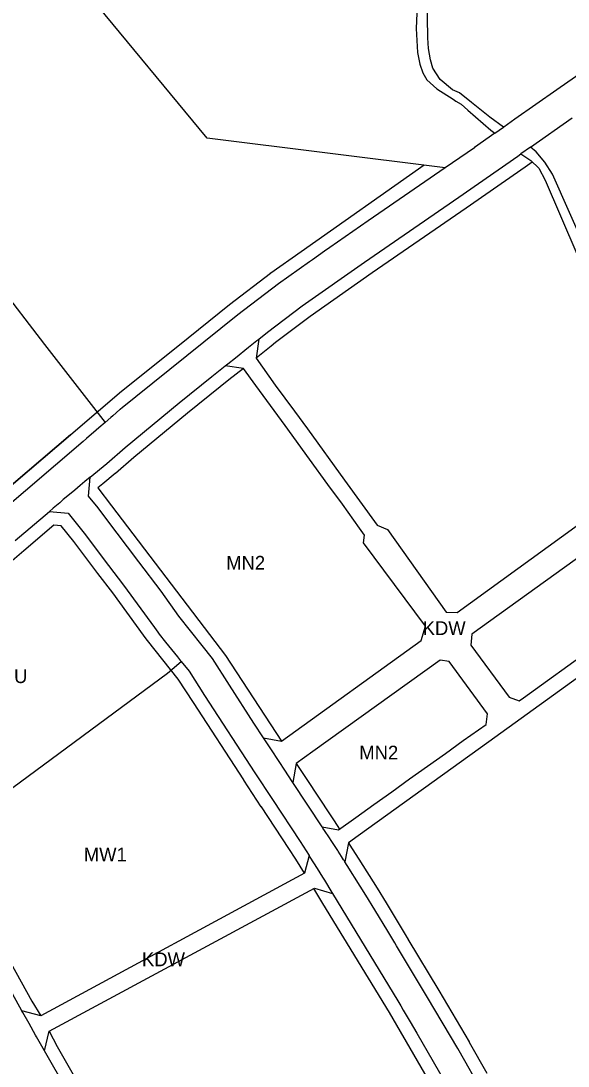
# Model space of a CAD drawing. Extents: x 7435758 to 7439981, y 5550649 to 5554049.
# Drawn here: x 7437642.5 to 7437849, y 5551609 to 5552003.8 of the extents above; entities that cross this region are included whole.
import ezdxf

# ---------------------------------------------------------------- set-up
doc = ezdxf.new("R2010")
doc.units = 0
for name, color, linetype in [('linie_rozgraniczające', 7, 'Continuous'), ('linie_zabudowy_nieprzekraczalne', 7, 'Continuous'), ('oznaczenia_przeznaczen', 7, 'Continuous')]:
    doc.layers.add(name, color=color, linetype=linetype)

msp = doc.modelspace()

# ---------------------------------------------------------------- linework, layer by layer
at = {"layer": 'linie_rozgraniczające'}
for p, q in [((7437712.83, 5551959.48), (7437577.43, 5552123.38)), ((7437796.11, 5551997.41), (7437795.23, 5552040.98)), ((7437792.45, 5552018.67), (7437791.72, 5552000.89)), ((7437791.72, 5552000.89), (7437792.18, 5551991.78)), ((7437796.28, 5551993.3), (7437796.11, 5551997.41)), ((7437792.18, 5551991.78), (7437793.09, 5551987.39)), ((7437797.12, 5551989.1), (7437796.28, 5551993.3)), ((7437793.09, 5551987.39), (7437794.21, 5551984.18)), ((7437797.95, 5551985.86), (7437797.12, 5551989.1)), ((7437800.76, 5551981.58), (7437797.95, 5551985.86)), ((7437794.21, 5551984.18), (7437795.76, 5551981.53)), ((7437854.78, 5551984.69), (7437844.78, 5551977.68)), ((7437795.76, 5551981.53), (7437799.51, 5551978.16)), ((7437799.51, 5551978.16), (7437805.64, 5551974.16)), ((7437805.36, 5551977.76), (7437800.76, 5551981.58)), ((7437808.05, 5551976.66), (7437805.36, 5551977.76)), ((7437805.64, 5551974.16), (7437806.67, 5551973.51)), ((7437812.58, 5551972.99), (7437808.05, 5551976.66)), ((7437844.78, 5551977.68), (7437828.97, 5551966.61)), ((7437806.67, 5551973.51), (7437808.61, 5551972.29)), ((7437808.61, 5551972.29), (7437811.23, 5551970.05)), ((7437811.23, 5551970.05), (7437819.85, 5551962.54)), ((7437819.46, 5551967.45), (7437812.58, 5551972.99)), ((7437824.7, 5551963.61), (7437819.46, 5551967.45)), ((7437828.97, 5551966.61), (7437824.78, 5551963.66)), ((7437834.89, 5551956.1), (7437850.63, 5551967.13)), ((7437819.85, 5551962.54), (7437821.43, 5551961.32)), ((7437821.43, 5551961.32), (7437824.7, 5551963.61)), ((7437824.78, 5551963.66), (7437824.7, 5551963.61)), ((7437802.61, 5551948.27), (7437712.83, 5551959.48)), ((7437821.43, 5551961.32), (7437813.73, 5551955.92)), ((7437813.65, 5551955.89), (7437802.61, 5551948.27)), ((7437813.66, 5551955.87), (7437813.65, 5551955.89)), ((7437813.73, 5551955.92), (7437813.66, 5551955.87)), ((7437834.89, 5551956.1), (7437831.21, 5551953.52)), ((7437837.03, 5551954.33), (7437834.89, 5551956.1)), ((7437840.29, 5551950.48), (7437837.03, 5551954.33)), ((7437807.74, 5551937.2), (7437830.01, 5551952.68)), ((7437830.01, 5551952.68), (7437830.04, 5551952.7)), ((7437830.04, 5551952.7), (7437831.21, 5551953.52)), ((7437831.21, 5551953.52), (7437834.97, 5551951.01)), ((7437834.97, 5551951.01), (7437837.94, 5551948.15)), ((7437843.13, 5551945.94), (7437840.29, 5551950.48)), ((7437802.61, 5551948.27), (7437777.58, 5551930.98)), ((7437837.94, 5551948.15), (7437840.36, 5551943.66)), ((7437840.36, 5551943.66), (7437852.28, 5551915.86)), ((7437855.94, 5551916.89), (7437843.13, 5551945.94)), ((7437772.17, 5551912.67), (7437807.74, 5551937.2)), ((7437777.58, 5551930.98), (7437773.57, 5551928.21)), ((7437773.57, 5551928.21), (7437759.14, 5551918.25)), ((7437757.12, 5551916.83), (7437752.5, 5551913.57)), ((7437759.14, 5551918.25), (7437757.12, 5551916.83)), ((7437627.25, 5551912.88), (7437651.38, 5551881.6)), ((7437751.4, 5551912.79), (7437739.68, 5551904.52)), ((7437748.7, 5551896.2), (7437772.17, 5551912.67)), ((7437752.15, 5551913.32), (7437751.4, 5551912.79)), ((7437752.5, 5551913.57), (7437752.15, 5551913.32)), ((7437739.68, 5551904.52), (7437724.32, 5551892.73)), ((7437735.5, 5551886.21), (7437748.7, 5551896.2)), ((7437724.32, 5551892.73), (7437685.84, 5551861.8)), ((7437732.24, 5551883.6), (7437731.24, 5551876.4)), ((7437731.52, 5551883.02), (7437732.24, 5551883.6)), ((7437732.24, 5551883.6), (7437735.5, 5551886.21)), ((7437651.38, 5551881.6), (7437674.25, 5551852.12)), ((7437723.47, 5551876.58), (7437728.36, 5551880.49)), ((7437728.36, 5551880.49), (7437731.52, 5551883.02)), ((7437720.62, 5551874.3), (7437723.47, 5551876.58)), ((7437731.24, 5551876.4), (7437738.41, 5551866.24)), ((7437714.52, 5551869.41), (7437719.6, 5551873.48)), ((7437719.6, 5551873.48), (7437720.62, 5551874.3)), ((7437726.51, 5551872.44), (7437719.6, 5551873.48)), ((7437731.2, 5551866.04), (7437726.51, 5551872.44)), ((7437702.19, 5551859.51), (7437714.52, 5551869.41)), ((7437742.22, 5551851.01), (7437731.2, 5551866.04)), ((7437738.41, 5551866.24), (7437745.69, 5551856.39)), ((7437681.86, 5551842.68), (7437702.19, 5551859.51)), ((7437685.84, 5551861.8), (7437681.99, 5551858.68)), ((7437679.84, 5551856.95), (7437677.13, 5551854.61)), ((7437679.98, 5551857.06), (7437679.84, 5551856.95)), ((7437680.88, 5551857.78), (7437679.98, 5551857.06)), ((7437681.99, 5551858.68), (7437680.88, 5551857.78)), ((7437745.69, 5551856.39), (7437750.65, 5551849.65)), ((7437674.25, 5551852.12), (7437671.9, 5551850.1)), ((7437676.47, 5551854.04), (7437674.25, 5551852.12)), ((7437677.13, 5551854.61), (7437676.47, 5551854.04)), ((7437670.89, 5551849.23), (7437667.25, 5551846.09)), ((7437671.9, 5551850.1), (7437670.89, 5551849.23)), ((7437742.22, 5551851), (7437742.22, 5551851.01)), ((7437751.47, 5551838.2), (7437742.22, 5551851)), ((7437750.65, 5551849.65), (7437764.61, 5551830.36)), ((7437665.96, 5551844.96), (7437632.46, 5551816.42)), ((7437667.24, 5551846.05), (7437665.96, 5551844.96)), ((7437667.25, 5551846.05), (7437667.24, 5551846.05)), ((7437667.25, 5551846.09), (7437667.25, 5551846.05)), ((7437674.9, 5551836.66), (7437681.86, 5551842.68)), ((7437668.66, 5551831.46), (7437674.9, 5551836.66)), ((7437758.35, 5551828.7), (7437751.47, 5551838.2)), ((7437664.79, 5551828.24), (7437662.82, 5551826.59)), ((7437666.62, 5551829.76), (7437664.79, 5551828.24)), ((7437668.66, 5551831.46), (7437666.62, 5551829.76)), ((7437667.96, 5551824.32), (7437668.66, 5551831.46)), ((7437763.84, 5551821.23), (7437758.35, 5551828.7)), ((7437764.61, 5551830.36), (7437776.99, 5551813.28)), ((7437662.82, 5551826.59), (7437659.51, 5551823.84)), ((7437671.6, 5551819.82), (7437667.96, 5551824.32)), ((7437807.11, 5551780.31), (7437871.35, 5551826.92)), ((7437657.13, 5551821.81), (7437654.66, 5551819.7)), ((7437658.48, 5551822.96), (7437657.13, 5551821.81)), ((7437659.51, 5551823.84), (7437658.48, 5551822.96)), ((7437770.29, 5551812.25), (7437763.84, 5551821.23)), ((7437640.35, 5551807.5), (7437653.28, 5551818.53)), ((7437654.66, 5551819.7), (7437653.28, 5551818.53)), ((7437653.28, 5551818.53), (7437660.32, 5551817.86)), ((7437660.32, 5551817.86), (7437666.39, 5551810.24)), ((7437674.59, 5551815.98), (7437671.6, 5551819.82)), ((7437877.2, 5551818.71), (7437812.75, 5551772.12)), ((7437687.04, 5551799.53), (7437674.59, 5551815.98)), ((7437772.17, 5551809.6), (7437770.29, 5551812.25)), ((7437776.99, 5551813.28), (7437780.9, 5551811.67)), ((7437666.39, 5551810.24), (7437675.56, 5551798.13)), ((7437771.76, 5551806.62), (7437772.17, 5551809.6)), ((7437780.9, 5551811.67), (7437803.06, 5551780.46)), ((7437795.17, 5551775.15), (7437771.76, 5551806.62)), ((7437675.56, 5551798.13), (7437681.15, 5551790.72)), ((7437695.36, 5551788.35), (7437687.04, 5551799.53)), ((7437681.15, 5551790.72), (7437692.85, 5551774.66)), ((7437702.04, 5551778.99), (7437695.36, 5551788.35)), ((7437710.94, 5551767.9), (7437702.04, 5551778.99)), ((7437803.06, 5551780.46), (7437807.11, 5551780.31)), ((7437692.85, 5551774.66), (7437694.15, 5551772.85)), ((7437694.15, 5551772.85), (7437694.43, 5551772.51)), ((7437793.51, 5551769.78), (7437795.17, 5551775.15)), ((7437694.43, 5551772.51), (7437694.7, 5551772.16)), ((7437694.7, 5551772.16), (7437697.09, 5551769.19)), ((7437697.09, 5551769.19), (7437701.61, 5551763.54)), ((7437740.84, 5551731.77), (7437793.51, 5551769.78)), ((7437812.75, 5551772.12), (7437812.29, 5551768.05)), ((7437714.81, 5551763.01), (7437710.94, 5551767.9)), ((7437812.29, 5551768.05), (7437826.8, 5551748.37)), ((7437866.87, 5551766.02), (7437819.07, 5551731.54)), ((7437832.18, 5551748.17), (7437860.01, 5551768.18)), ((7437697.86, 5551757.42), (7437703.01, 5551761.8)), ((7437701.61, 5551763.54), (7437702.78, 5551762.08)), ((7437702.78, 5551762.08), (7437702.87, 5551761.97)), ((7437702.87, 5551761.97), (7437702.97, 5551761.85)), ((7437702.97, 5551761.85), (7437703.01, 5551761.8)), ((7437703.01, 5551761.8), (7437705.95, 5551758.13)), ((7437721.23, 5551752.85), (7437714.81, 5551763.01)), ((7437800.68, 5551762.28), (7437752.72, 5551727.88)), ((7437804.12, 5551761.79), (7437800.68, 5551762.28)), ((7437818.64, 5551742.12), (7437804.12, 5551761.79)), ((7437608.38, 5551691.31), (7437697.86, 5551757.42)), ((7437705.95, 5551758.13), (7437711.81, 5551749.05)), ((7437711.81, 5551749.05), (7437730.8, 5551719.8)), ((7437730.46, 5551738.54), (7437721.23, 5551752.85)), ((7437826.8, 5551748.37), (7437830.59, 5551747.03)), ((7437830.59, 5551747.03), (7437832.18, 5551748.17)), ((7437818.07, 5551738.09), (7437818.64, 5551742.12)), ((7437734.09, 5551733.01), (7437730.46, 5551738.54)), ((7437809.48, 5551731.95), (7437818.07, 5551738.09)), ((7437736.81, 5551728.86), (7437734.09, 5551733.01)), ((7437734.09, 5551733.01), (7437740.84, 5551731.77)), ((7437819.07, 5551731.54), (7437769.74, 5551695.94)), ((7437802.72, 5551727.13), (7437809.48, 5551731.95)), ((7437737.1, 5551728.42), (7437736.81, 5551728.86)), ((7437742.35, 5551720.44), (7437737.1, 5551728.42)), ((7437752.72, 5551727.88), (7437746.4, 5551723.35)), ((7437795.96, 5551722.3), (7437802.72, 5551727.13)), ((7437746.4, 5551723.35), (7437745.15, 5551716.18)), ((7437789.21, 5551717.48), (7437795.96, 5551722.3)), ((7437730.8, 5551719.8), (7437737.41, 5551709.74)), ((7437743.24, 5551719.08), (7437742.35, 5551720.44)), ((7437745.15, 5551716.18), (7437743.24, 5551719.08)), ((7437782.46, 5551712.64), (7437789.21, 5551717.48)), ((7437756.16, 5551699.44), (7437745.15, 5551716.18)), ((7437737.41, 5551709.74), (7437747.86, 5551693.88)), ((7437775.71, 5551707.81), (7437782.46, 5551712.64)), ((7437768.96, 5551702.97), (7437775.71, 5551707.81)), ((7437762.38, 5551698.26), (7437768.96, 5551702.97)), ((7437756.5, 5551698.93), (7437756.16, 5551699.44)), ((7437756.16, 5551699.44), (7437762.38, 5551698.26)), ((7437757.1, 5551698.02), (7437756.5, 5551698.93)), ((7437757.13, 5551697.98), (7437757.1, 5551698.02)), ((7437758.92, 5551695.26), (7437757.13, 5551697.98)), ((7437747.86, 5551693.88), (7437751.24, 5551688.54)), ((7437759.61, 5551694.2), (7437758.92, 5551695.26)), ((7437762.07, 5551690.41), (7437759.61, 5551694.2)), ((7437769.74, 5551695.94), (7437766.13, 5551693.34)), ((7437762.19, 5551690.22), (7437762.07, 5551690.41)), ((7437763.48, 5551688.17), (7437762.19, 5551690.22)), ((7437766.13, 5551693.34), (7437764.77, 5551686.13)), ((7437751.24, 5551688.54), (7437749.48, 5551681.86)), ((7437751.24, 5551688.54), (7437751.6, 5551687.96)), ((7437751.6, 5551687.96), (7437752.96, 5551685.82)), ((7437752.96, 5551685.82), (7437754.29, 5551683.71)), ((7437764.25, 5551686.95), (7437763.48, 5551688.17)), ((7437764.46, 5551686.62), (7437764.25, 5551686.95)), ((7437764.77, 5551686.13), (7437764.46, 5551686.62)), ((7437765.6, 5551684.81), (7437764.77, 5551686.13)), ((7437749.48, 5551681.86), (7437650.01, 5551628.04)), ((7437754.29, 5551683.71), (7437754.3, 5551683.71)), ((7437754.3, 5551683.71), (7437756.33, 5551680.37)), ((7437770.51, 5551677.02), (7437765.6, 5551684.81)), ((7437756.33, 5551680.37), (7437757.05, 5551679.19)), ((7437757.05, 5551679.19), (7437759.81, 5551674.64)), ((7437653.08, 5551622.16), (7437753.28, 5551676.25)), ((7437753.28, 5551676.25), (7437760.06, 5551674.24)), ((7437759.81, 5551674.64), (7437760.06, 5551674.24)), ((7437760.06, 5551674.24), (7437784.75, 5551633.67)), ((7437772.72, 5551673.52), (7437770.51, 5551677.02)), ((7437776.12, 5551668.07), (7437772.72, 5551673.52)), ((7437780.98, 5551659.98), (7437776.12, 5551668.07)), ((7437783.62, 5551655.58), (7437780.98, 5551659.98)), ((7437783.61, 5551655.56), (7437783.62, 5551655.58)), ((7437784.29, 5551654.45), (7437783.61, 5551655.56)), ((7437795.92, 5551634.99), (7437784.29, 5551654.45)), ((7437642.86, 5551629.92), (7437629.36, 5551654.17)), ((7437807.38, 5551615.63), (7437795.92, 5551634.99)), ((7437784.75, 5551633.67), (7437785.86, 5551631.84)), ((7437785.86, 5551631.84), (7437786.82, 5551630.18)), ((7437643.23, 5551629.25), (7437642.86, 5551629.92)), ((7437650.01, 5551628.04), (7437642.86, 5551629.92)), ((7437645.57, 5551625.05), (7437643.23, 5551629.25)), ((7437786.82, 5551630.18), (7437789.4, 5551625.73)), ((7437647.97, 5551620.75), (7437645.57, 5551625.05)), ((7437789.4, 5551625.73), (7437791.88, 5551621.44)), ((7437648.35, 5551620.09), (7437647.97, 5551620.75)), ((7437650.87, 5551615.67), (7437648.35, 5551620.09)), ((7437651.34, 5551614.85), (7437653.08, 5551622.16)), ((7437791.88, 5551621.44), (7437814.86, 5551581.73)), ((7437651.34, 5551614.85), (7437650.87, 5551615.67)), ((7437701.57, 5551526.92), (7437651.34, 5551614.85)), ((7437810.02, 5551611.01), (7437807.38, 5551615.63)), ((7437814.48, 5551603.18), (7437810.02, 5551611.01))]:
    msp.add_line(p, q, dxfattribs=at)
at = {"layer": 'linie_zabudowy_nieprzekraczalne'}
msp.add_line((7437661.22, 5551847.49), (7437629.25, 5551820.25), dxfattribs=at)
for points in [[(7437835.42, 5551950.37), (7437832.87, 5551948.58), (7437832.86, 5551948.57), (7437810.59, 5551933.09), (7437810.58, 5551933.08), (7437775.02, 5551908.57), (7437751.64, 5551892.16), (7437738.57, 5551882.27), (7437736.92, 5551880.95), (7437731.24, 5551876.4)], [(7437629.25, 5551820.25), (7437661.22, 5551847.49), (7437661.27, 5551847.53), (7437680.48, 5551863.89), (7437701.66, 5551880.93), (7437721.18, 5551896.63), (7437721.27, 5551896.7), (7437736.63, 5551908.49), (7437736.73, 5551908.57), (7437736.8, 5551908.61), (7437748.24, 5551916.68), (7437794.67, 5551949.43)], [(7437726.51, 5551872.44), (7437721.02, 5551868.21), (7437717.65, 5551865.51), (7437705.36, 5551855.64), (7437685.08, 5551838.86), (7437678.17, 5551832.88), (7437678.1, 5551832.82), (7437673.44, 5551828.94), (7437671.49, 5551827.37), (7437676.61, 5551820.64), (7437719.71, 5551764.14), (7437740.84, 5551731.77)], [(7437749.53, 5551681.89), (7437746.21, 5551687.13), (7437743.66, 5551691.16), (7437733.24, 5551706.99), (7437733.23, 5551706.99), (7437726.62, 5551717.06), (7437726.61, 5551717.08), (7437707.61, 5551746.33), (7437707.6, 5551746.34), (7437701.89, 5551755.2), (7437690.25, 5551769.72), (7437690.11, 5551769.9), (7437690.09, 5551769.93), (7437688.8, 5551771.73), (7437677.14, 5551787.75), (7437671.57, 5551795.12), (7437662.44, 5551807.17), (7437657.73, 5551813.08), (7437654.91, 5551813.35), (7437643.59, 5551803.69), (7437623.14, 5551786.26)], [(7437746.4, 5551723.35), (7437750.42, 5551717.27), (7437759.18, 5551703.96), (7437760.68, 5551701.68), (7437762.74, 5551698.55)], [(7437766.13, 5551693.34), (7437766.39, 5551692.94), (7437766.41, 5551692.9), (7437766.42, 5551692.89), (7437770.05, 5551687.13), (7437776.95, 5551676.18), (7437776.96, 5551676.17), (7437780.36, 5551670.72), (7437780.41, 5551670.64), (7437787.9, 5551658.15), (7437788.01, 5551657.97), (7437788.06, 5551657.88), (7437788.56, 5551657.05), (7437788.58, 5551657.01), (7437800.21, 5551637.56), (7437800.22, 5551637.54), (7437811.69, 5551618.17), (7437811.73, 5551618.1), (7437818.39, 5551606.38)], [(7437653.08, 5551622.16), (7437656.22, 5551616.38), (7437705.89, 5551529.43), (7437723.44, 5551499.81), (7437733, 5551497.15), (7437785.39, 5551527.59), (7437824.77, 5551550.9), (7437825.49, 5551551.92), (7437825.39, 5551552.78), (7437824.87, 5551554.79), (7437810.55, 5551579.2), (7437810.53, 5551579.23), (7437781.56, 5551629.29), (7437756.5, 5551670.46), (7437753.06, 5551676.12)], [(7437633.73, 5551656.6), (7437646.55, 5551633.57), (7437650.01, 5551628.04)]]:
    msp.add_lwpolyline(points, dxfattribs=at)

# ---------------------------------------------------------------- texts
at = {"layer": 'oznaczenia_przeznaczen'}
for s, p in [('MN2', (7437719.97, 5551796.52)), ('KDW', (7437794.14, 5551771.83)), ('MU', (7437634.09, 5551753.68)), ('MN2', (7437770.22, 5551724.82)), ('MW1', (7437666.22, 5551686.36)), ('KDW', (7437688.18, 5551646.75))]:
    msp.add_text(s, height=5.2, dxfattribs=at).set_placement(p)

doc.saveas('drawing.dxf')
